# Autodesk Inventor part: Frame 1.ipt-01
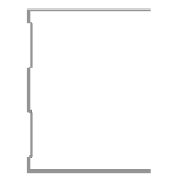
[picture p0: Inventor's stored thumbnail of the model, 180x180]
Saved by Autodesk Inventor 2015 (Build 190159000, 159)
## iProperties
Created: 2015-04
Part Number: Frame 1.ipt-01
Material: Aluminum 6061
Document SubType Name: Modeling
Standard: Unnamed
Designer: suporte
Language: en-US
Size Designation: (Unnamed 1)
Categories: <MemberInstance><Categories><Category DisplayName="Structural Shapes" InternalName="089c4875-fa83-4c05-b084-43b9cc11f5ed" Mnemonic="GRDR"><CategoryParameter Dis
Density: 2.7 g/cm^3
Appearance: Aluminum - Flat
G_L: 2100,000 mm
G_W: 70,000 mm
G_H: 75,000 mm
IsCustomPart: 1
Author: suporte
_CCFamilyMember: 1
_CCFamilyDisplayName: Frame 1
_FrameMemberDoc: Frame Member File
_Version: 15.0.0
_GetPNFromCC: 1
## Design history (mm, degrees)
node "Start Plane"
node "End Plane"
sketch "Sketch"
  geometry: L1 (34.6, 37.5)-(34.6, 36.7); L2 (34.6, 36.7)-(-34.6, 36.7); L3 (-34.6, -36.7)-(34.6, -36.7); L4 (34.6, -36.7)-(34.6, -37.5); L5 (34.6, -37.5)-(-35.4, -37.5); L6 (-35.4, 37.5)-(34.6, 37.5); L7 (-34.6, 36.7)-(-34.6, 31.7); L8 (-34.6, 31.7)-(-33.4, 30.5); L9 (-33.4, 30.5)-(-33.4, 10.746); L10 (-33.4, 10.746)-(-34.6, 9.546); L11 (-34.6, 9.546)-(-34.6, -9.546); L12 (-34.6, -9.546)-(-33.4, -10.746); L13 (-33.4, -10.746)-(-33.4, -30.5); L14 (-33.4, -30.5)-(-34.6, -31.7); L15 (-34.6, -31.7)-(-34.6, -36.7); L16 (-35.4, -37.5)-(-35.4, -31.369); L17 (-35.4, -31.369)-(-34.2, -30.169); L18 (-34.2, -30.169)-(-34.2, -11.077); L19 (-34.2, -11.077)-(-35.4, -9.877); L20 (-35.4, -9.877)-(-35.4, 9.877); L21 (-35.4, 9.877)-(-34.2, 11.077); L22 (-34.2, 11.077)-(-34.2, 30.169); L23 (-34.2, 30.169)-(-35.4, 31.369); L24 (-35.4, 31.369)-(-35.4, 37.5); L25 (-35.4, 0)-(30.37, 0); 3 further points
  constraints: 50 end point, 10 point on line, 9 parallel, 5 perpendicular, 4 equal length, 3 midpoint, 3 vertical, 2 vertical alignment, 1 collinear, 1 horizontal, 1 horizontal alignment
  dimensions: "d3" = 0.8 distance of L1.start L1.end; "d5" = 75 distance between parallel lines of L5 L6; "d6" = 0.8 distance between parallel lines of L24 L7; "d7" = 0.8 distance between parallel lines of L8 L23; "d8" = 0.8 distance between parallel lines of L22 L9; "d9" = 0.8 distance between parallel lines of L17 L14; "d10" = 0.8 distance between parallel lines of L13 L18; "d11" = 0.8 distance between parallel lines of L12 L19; "d12" = 0.8 distance between parallel lines of L21 L10; "d13" = 5 distance of L2.end L7.end; "d15" = 135 deg angle of L9 L8; "d16" = 2 distance between parallel lines of L24 L9; "d17" = 70 distance of L6.start L1.start
extrude "Body" join sketch "Sketch" stored distance "d24" = 0.13; taper "d25" = 0 deg
node "Driven Length"
  sketch "Sketch8"
    geometry: L1 (0, 0)-(10, 0) reference
    constraints: 2 end point, 1 horizontal
  workplane "Work Plane6"
  sketch "Sketch9"
    geometry: L1 (-2, 0)-(12, 0) reference; L2 (-2, 2100)-(12, 2100) reference
    dimensions: "d27" = 2100 distance between parallel lines of L1 L2 (derived)
body "Solid1"
other parameters: "G_OFFSET_START" = 0 [user parameter; used in 1 equation term], "G_OFFSET_END" = 0 [user parameter; used in 1 equation term], "d22" = 0 (computed from G_OFFSET_START), "G_L" = 2100 (= d27) [user parameter], "d32" = 90 deg
